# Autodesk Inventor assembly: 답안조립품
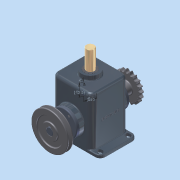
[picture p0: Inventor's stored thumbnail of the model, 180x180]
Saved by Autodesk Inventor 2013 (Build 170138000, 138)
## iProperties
Created: 2015-03
Part Number: 답안조립품
Document SubType Name: Assembly
Designer: Administrator
Mass: 8579.22 g
Surface Area: 4386.56 cm^2
Volume: 1982.53 cm^3
Density: 4.32741 g/cm^3
Author: Administrator
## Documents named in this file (15)
- C:\Documents and Settings\Administrator\바탕 화면\350305V1015\답안조립품.iam
- C:\Documents and Settings\Administrator\바탕 화면\350305V1015\본체.ipt
- C:\Documents and Settings\Administrator\바탕 화면\350305V1015\베어링 6205.ipt
- C:\Documents and Settings\Administrator\바탕 화면\350305V1015\커버.ipt
- C:\Documents and Settings\Administrator\바탕 화면\350305V1015\편심축.ipt
- C:\Documents and Settings\Administrator\바탕 화면\350305V1015\멈춤링.ipt
- C:\Documents and Settings\Administrator\바탕 화면\350305V1015\오일실.ipt
- C:\Documents and Settings\Administrator\바탕 화면\350305V1015\키 8x8.ipt
- C:\Documents and Settings\Administrator\바탕 화면\350305V1015\V-벨트풀리.ipt
- C:\Documents and Settings\Administrator\바탕 화면\350305V1015\체인 스프로킷.ipt
- C:\Documents and Settings\Administrator\바탕 화면\350305V1015\M4x0.5.ipt
- C:\Documents and Settings\Administrator\바탕 화면\350305V1015\멈춤나사 M5x0.5.ipt
- C:\Documents and Settings\Administrator\바탕 화면\350305V1015\슬라이드.ipt
- C:\Documents and Settings\Administrator\바탕 화면\350305V1015\부시.ipt
- C:\Documents and Settings\Administrator\바탕 화면\350305V1015\7-가변스프링.ipt
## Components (9 placed, 4 different names)
1. V-벨트풀리:1 — 각도:3, 플러쉬:1
2. 5-체인 스프로킷:1 — 각도:4, 플러쉬:2
3. 7-가변스프링:1
4. M4x0.5:2
5. M4x0.5:3
6. M4x0.5:4
7. M4x0.5:1
8. M4x0.5:5
9. M4x0.5:6
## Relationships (4: Angle 2, Flush 2)
- 각도:3 [Angle]: V-벨트풀리:1
- 플러쉬:1 [Flush]: V-벨트풀리:1
- 각도:4 [Angle]: 5-체인 스프로킷:1
- 플러쉬:2 [Flush]: 5-체인 스프로킷:1
